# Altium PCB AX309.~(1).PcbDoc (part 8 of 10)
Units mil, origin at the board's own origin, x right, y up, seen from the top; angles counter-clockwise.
Board outline 5185 x 3614 mil, 4 copper layers (Top Layer, GND, Mid-Layer 1, Bottom Layer); 191 components, 352 nets, 1106 pads, 425 vias.
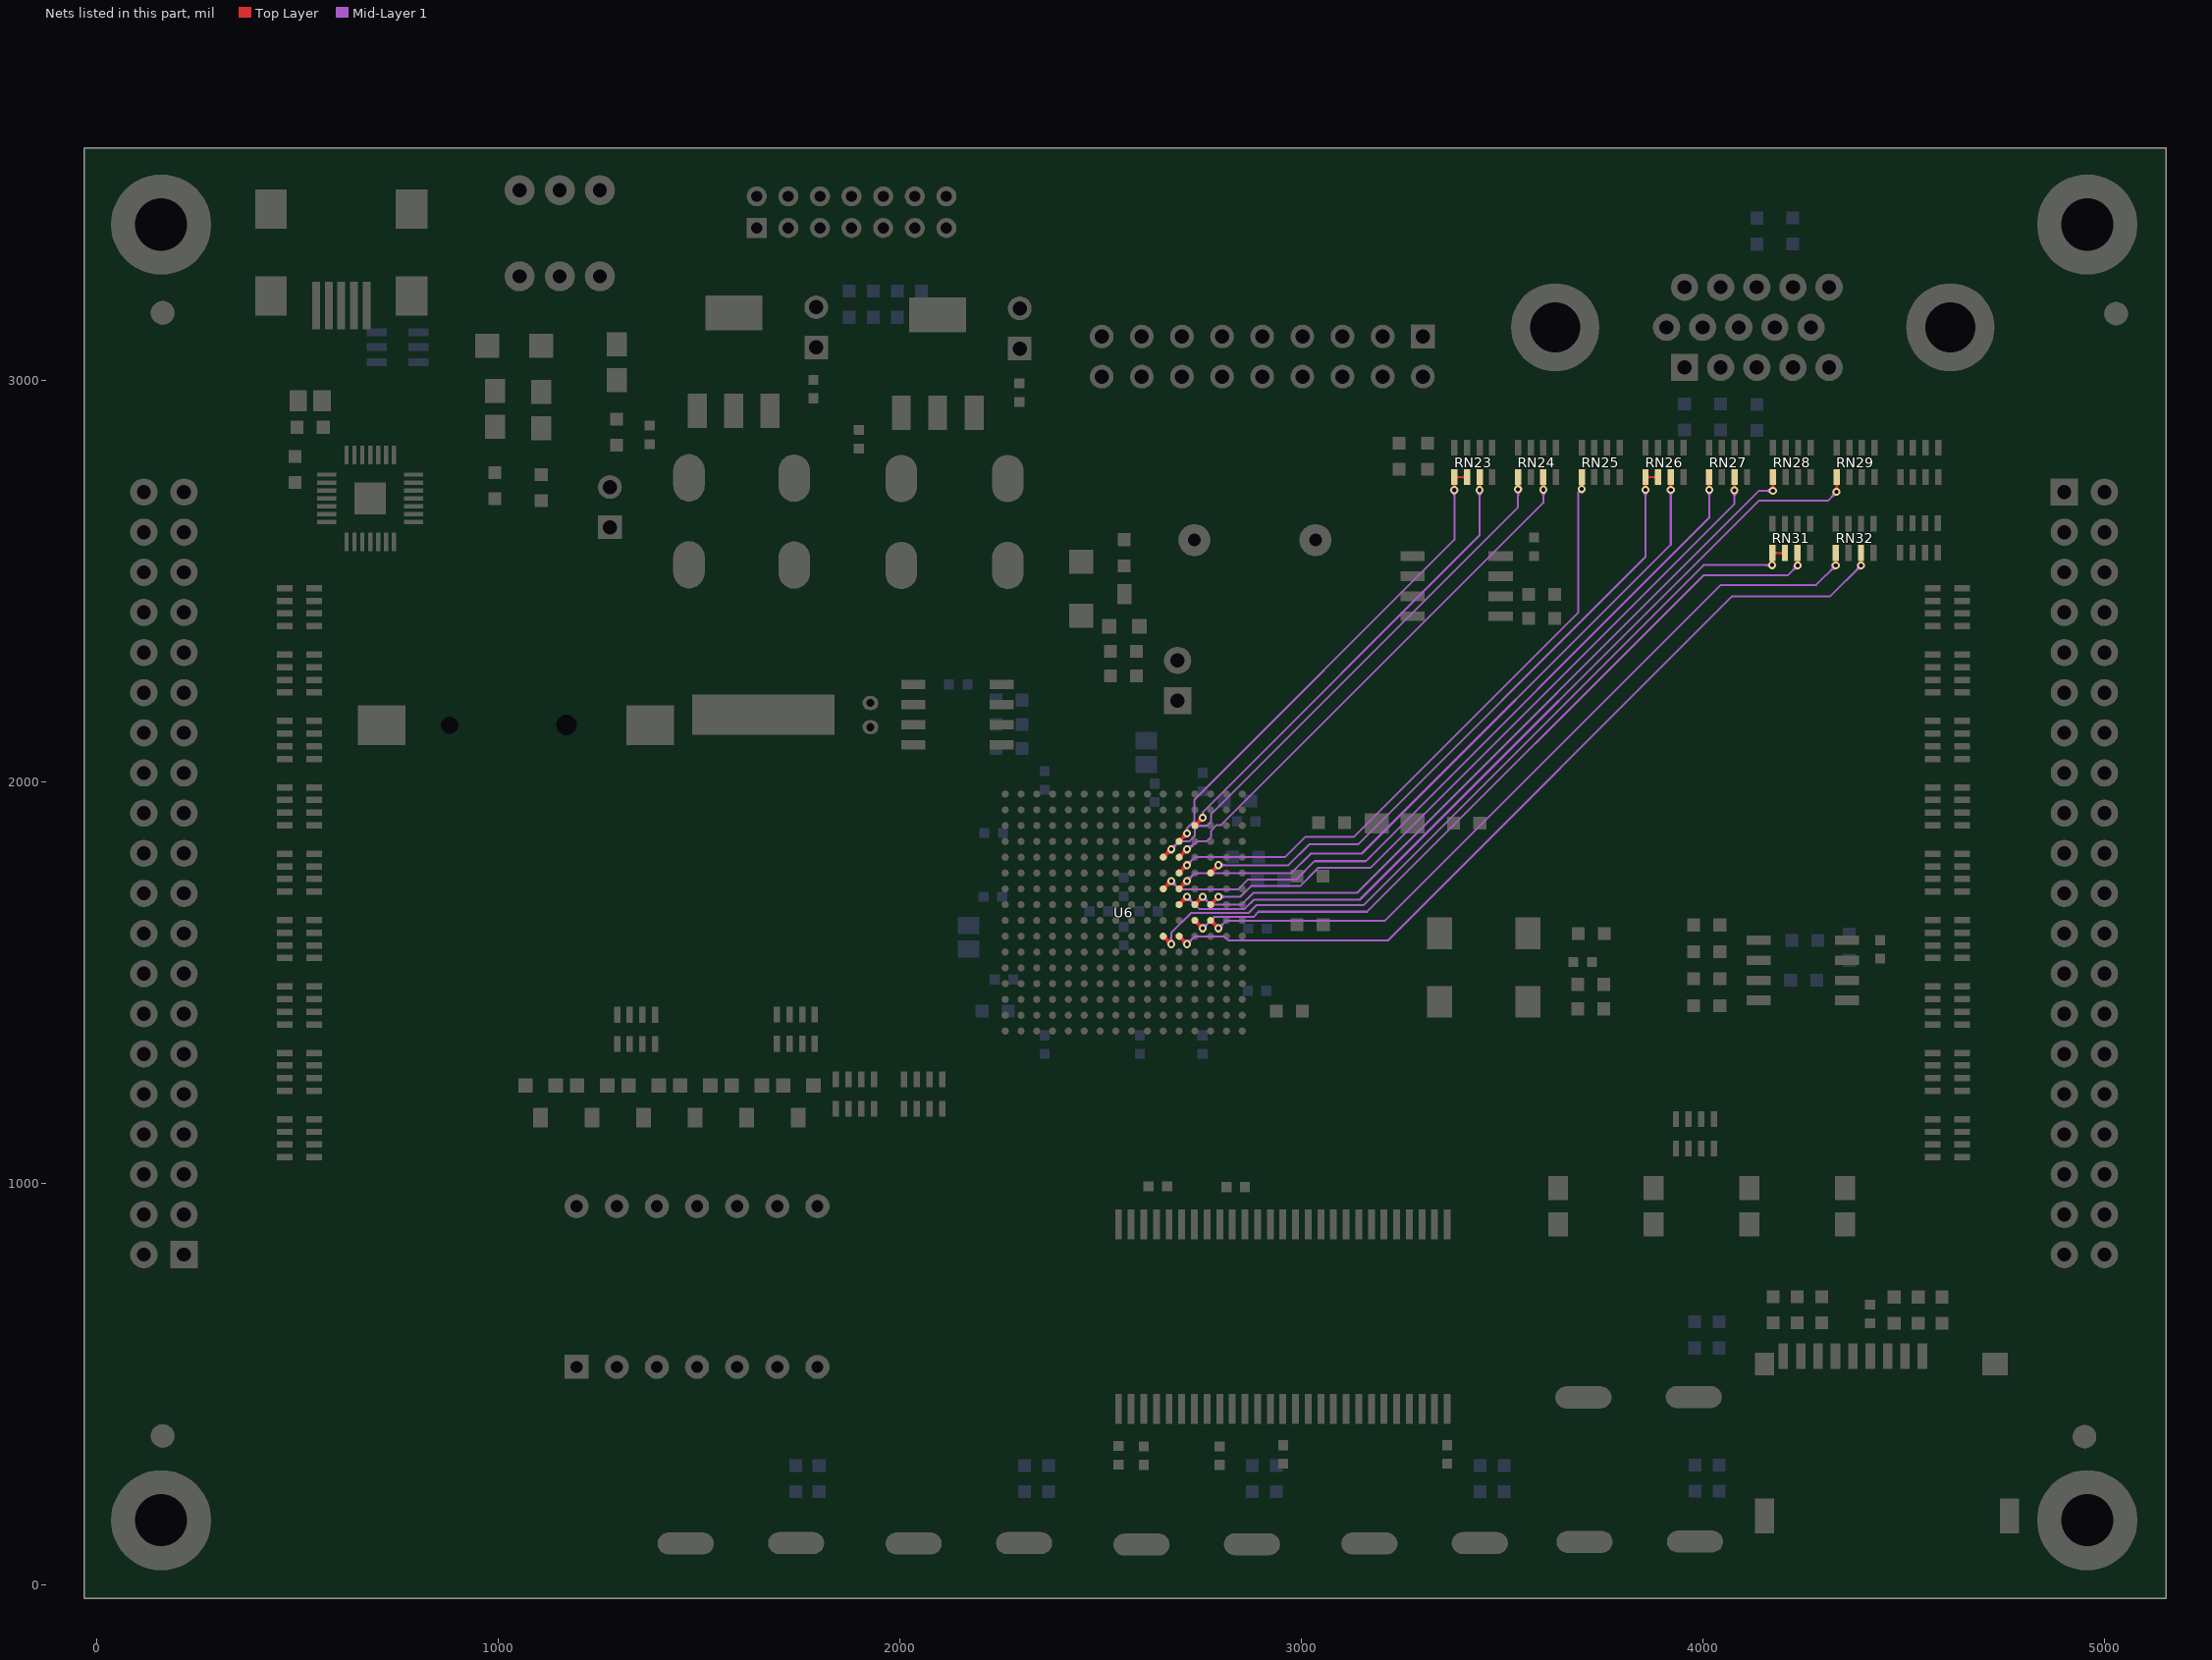
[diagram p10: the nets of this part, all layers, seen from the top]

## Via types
v1: diameter 20, hole 10, Top Layer to Bottom Layer, 328 vias
v2: diameter 30, hole 15, Top Layer to Bottom Layer, 95 vias
v3: diameter 40, hole 20, Top Layer to Bottom Layer, 2 vias

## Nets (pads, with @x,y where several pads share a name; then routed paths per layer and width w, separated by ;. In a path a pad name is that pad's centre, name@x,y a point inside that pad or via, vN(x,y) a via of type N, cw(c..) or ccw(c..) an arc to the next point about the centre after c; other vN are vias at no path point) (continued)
VGAD1: RN32.7 U6.M7 | length 2410.8
  Top Layer w5: U6.M7@2695.8,1608.59 cw(c2695.8,1593.24) 2706.65,1604.09 cw(c2717.5,1614.94) U6.M7@2702.15,1614.94 ; U6.M7@2695.8,1614.94 v1(2715.48,1595.26) ; U6.M7@2698.15,1609 cw(c2688.07,1591.54) v1@2708.05,1594.25 ; U6.M7@2701.74,1612.59 ccw(c2719.2,1622.67) v1@2716.49,1602.69 ; 2705.03,1605.02 cw(c2701.58,1599.04) v1@2708.24,1597.23 ; 2705.72,1605.71 ccw(c2711.7,1609.16) v1@2713.51,1602.5 ; 2706.84,1603.76 ccw(c2717.47,1609.9) v1@2715.82,1597.74 ; 2706.98,1603.9 cw(c2700.84,1593.27) v1@2713,1594.92 ; v1@2707.98,1595.26 ccw(c2689.87,1595.26) 2702.68,1608.06 ccw(c2715.48,1620.87) v1@2715.48,1602.76 ; v1@4389.2,2543.8 ccw(c4376.4,2556.6) 4394.5,2556.6 ccw(c4412.61,2556.6) v1@4399.81,2543.8 ; RN32.7@4390.7,2554.24 cw(c4381.53,2545.07) 4394.5,2545.07 cw(c4407.48,2545.07) RN32.7@4398.3,2554.24 ; v1@4391.89,2545.52 ccw(c4390.96,2548.02) 4393.53,2548.71 ccw(c4397.61,2549.8) v1@4396.49,2545.73 ; v1@4392.52,2545.73 ccw(c4391.4,2549.8) 4395.48,2548.71 ccw(c4398.05,2548.02) v1@4397.12,2545.52 ; v1(4394.5,2538.5) RN32.7@4394.5,2569.85 ; 2707.53,1602.56 cw(c2701.41,1599.03) 2708.24,1597.2 ccw(c2701.41,1599.03) 2707.53,1602.56 ; 2708.18,1603.21 ccw(c2711.71,1609.33) 2713.54,1602.5 cw(c2711.71,1609.33) 2708.18,1603.21
  Mid-Layer 1 w5: v1(2715.48,1595.26) 2734.22,1614 2809,1614 2818,1605 3217,1605 4074,2462 4318.01,2462 v1(4394.5,2538.5) ; v1@2715.48,1602.76 ccw(c2715.48,1620.87) 2728.28,1608.06 ccw(c2741.09,1595.26) v1@2722.98,1595.26 ; v1@4387,2538.5 cw(c4368.9,2538.5) 4381.7,2525.69 cw(c4394.5,2512.89) v1@4394.5,2531
VGAD2: RN32.5 U6.P8 | length 2245.3
  Top Layer w5: U6.P8@2774.54,1647.96 cw(c2774.54,1632.61) 2785.39,1643.46 cw(c2796.24,1654.32) U6.P8@2780.89,1654.32 ; U6.P8@2774.54,1654.32 v1(2794.22,1634.63) ; U6.P8@2776.89,1648.37 cw(c2766.81,1630.91) v1@2786.79,1633.62 ; U6.P8@2780.48,1651.96 ccw(c2797.94,1662.04) v1@2795.23,1642.06 ; 2783.77,1644.39 cw(c2780.32,1638.41) v1@2786.98,1636.6 ; 2784.46,1645.08 ccw(c2790.44,1648.53) v1@2792.25,1641.87 ; 2785.58,1643.13 ccw(c2796.21,1649.27) v1@2794.56,1637.11 ; 2785.72,1643.27 cw(c2779.58,1632.64) v1@2791.74,1634.29 ; v1@2786.72,1634.63 ccw(c2768.61,1634.63) 2781.42,1647.43 ccw(c2794.22,1660.24) v1@2794.22,1642.13 ; v1@4326.21,2543.79 ccw(c4313.41,2556.59) 4331.51,2556.59 ccw(c4349.62,2556.59) v1@4336.82,2543.79 ; RN32.5@4327.71,2554.24 cw(c4318.54,2545.07) 4331.51,2545.07 cw(c4344.49,2545.07) RN32.5@4335.31,2554.24 ; v1@4328.89,2545.52 ccw(c4327.96,2548.01) 4330.54,2548.7 ccw(c4334.62,2549.8) v1@4333.5,2545.72 ; v1@4329.52,2545.72 ccw(c4328.4,2549.8) 4332.49,2548.7 ccw(c4335.06,2548.01) v1@4334.13,2545.52 ; v1(4331.51,2538.49) RN32.5@4331.51,2569.85 ; 2786.27,1641.93 cw(c2780.15,1638.4) 2786.98,1636.57 ccw(c2780.15,1638.4) 2786.27,1641.93 ; 2786.92,1642.58 ccw(c2790.45,1648.7) 2792.28,1641.87 cw(c2790.45,1648.7) 2786.92,1642.58
  Mid-Layer 1 w5: v1(2794.22,1634.63) 2812.59,1653 3208,1653 4045,2490 4283.02,2490 v1(4331.51,2538.49) ; v1@2794.22,1642.13 ccw(c2794.22,1660.24) 2807.02,1647.43 ccw(c2819.83,1634.63) v1@2801.72,1634.63 ; v1@4324.01,2538.49 cw(c4305.91,2538.49) 4318.71,2525.68 cw(c4331.51,2512.88) v1@4331.51,2530.99
VGAD3: RN31.7 U6.N8 | length 2189.7
  Top Layer w5: U6.N8@2735.17,1647.96 cw(c2735.17,1632.61) 2746.02,1643.46 cw(c2756.87,1654.32) U6.N8@2741.52,1654.32 ; U6.N8@2735.17,1654.32 v1(2754.85,1634.63) ; U6.N8@2737.52,1648.37 cw(c2727.44,1630.91) v1@2747.42,1633.62 ; U6.N8@2741.11,1651.96 ccw(c2758.57,1662.04) v1@2755.86,1642.06 ; 2744.4,1644.39 cw(c2740.95,1638.41) v1@2747.61,1636.6 ; 2745.09,1645.08 ccw(c2751.07,1648.53) v1@2752.88,1641.87 ; 2746.21,1643.13 ccw(c2756.84,1649.27) v1@2755.19,1637.11 ; 2746.35,1643.27 cw(c2740.21,1632.64) v1@2752.37,1634.29 ; v1@2747.35,1634.63 ccw(c2729.24,1634.63) 2742.05,1647.43 ccw(c2754.85,1660.24) v1@2754.85,1642.13 ; v1@4231.2,2543.8 ccw(c4218.4,2556.6) 4236.5,2556.6 ccw(c4254.61,2556.6) v1@4241.81,2543.8 ; RN31.7@4232.7,2554.24 cw(c4223.53,2545.07) 4236.5,2545.07 cw(c4249.48,2545.07) RN31.7@4240.3,2554.24 ; v1@4233.89,2545.52 ccw(c4232.96,2548.02) 4235.53,2548.71 ccw(c4239.61,2549.8) v1@4238.49,2545.73 ; v1@4234.52,2545.73 ccw(c4233.4,2549.8) 4237.48,2548.71 ccw(c4240.05,2548.02) v1@4239.12,2545.52 ; v1(4236.5,2538.5) RN31.7@4236.5,2569.85 ; v1@2752.91,1641.87 cw(c2751.08,1648.7) 2747.55,1642.58 ccw(c2751.08,1648.7) v1@2752.91,1641.87 ; 2746.9,1641.93 cw(c2740.78,1638.4) 2747.61,1636.57 ccw(c2740.78,1638.4) 2746.9,1641.93
  Mid-Layer 1 w5: v1(2754.85,1634.63) 2783.22,1663 2881,1663 2894,1676 3164,1676 4002,2514 4212.01,2514 v1(4236.5,2538.5) ; v1@2754.85,1642.13 ccw(c2754.85,1660.24) 2767.65,1647.43 ccw(c2780.46,1634.63) v1@2762.35,1634.63 ; v1@4229,2538.5 cw(c4210.9,2538.5) 4223.7,2525.69 cw(c4236.5,2512.89) v1@4236.5,2531
VGAD4: RN31.5 RN31.6 U6.L7 | length 2293.1
  Top Layer w5: U6.L7@2656.43,1608.59 cw(c2656.43,1593.24) 2667.28,1604.09 cw(c2678.13,1614.94) U6.L7@2662.78,1614.94 ; U6.L7@2656.43,1614.94 v1(2676.11,1595.26) ; U6.L7@2658.78,1609 cw(c2648.7,1591.54) v1@2668.68,1594.25 ; U6.L7@2662.37,1612.59 ccw(c2679.83,1622.67) v1@2677.12,1602.69 ; 2665.66,1605.02 cw(c2662.21,1599.04) v1@2668.87,1597.23 ; 2666.35,1605.71 ccw(c2672.33,1609.16) v1@2674.14,1602.5 ; 2667.47,1603.76 ccw(c2678.1,1609.9) v1@2676.45,1597.74 ; 2667.61,1603.9 cw(c2661.47,1593.27) v1@2673.63,1594.92 ; v1@2668.61,1595.26 ccw(c2650.5,1595.26) 2663.31,1608.06 ccw(c2676.11,1620.87) v1@2676.11,1602.76 ; v1@4168.21,2544.79 ccw(c4155.41,2557.59) 4173.51,2557.59 ccw(c4191.62,2557.59) v1@4178.82,2544.79 ; RN31.5@4169.71,2554.24 cw(c4160.54,2545.07) 4173.51,2545.07 cw(c4186.49,2545.07) RN31.5@4177.31,2554.24 ; v1(4173.51,2539.49) RN31.5@4173.51,2569.85 RN31.6@4205.01,2569.85 ; RN31.5@4177.31,2566.05 cw(c4186.49,2556.88) 4186.49,2569.85 cw(c4186.49,2582.82) RN31.5@4177.31,2573.65 ; RN31.6@4201.21,2566.05 ccw(c4192.03,2556.88) 4192.03,2569.85 ccw(c4192.03,2582.82) RN31.6@4201.21,2573.65 ; v1@2674.17,1602.5 cw(c2672.34,1609.33) 2668.81,1603.21 ccw(c2672.34,1609.33) v1@2674.17,1602.5 ; 2668.16,1602.56 cw(c2662.04,1599.03) 2668.87,1597.2 ccw(c2662.04,1599.03) 2668.16,1602.56
  Mid-Layer 1 w5: v1@2670.81,1600.56 ccw(c2658,1613.37) 2676.11,1613.37 ccw(c2694.22,1613.37) v1@2681.41,1600.56 ; v1(2676.11,1595.26) 2676.11,1623.11 2726,1673 2869,1673 2888,1692 3155,1692 4002.49,2539.49 v1(4173.51,2539.49) ; v1@4168.21,2534.18 ccw(c4155.41,2521.38) 4155.41,2539.49 ccw(c4155.41,2557.59) v1@4168.21,2544.79
VGAD5: RN29.5 U6.M9 | length 2383.6
  Top Layer w5: U6.M9@2695.8,1693.68 v1(2715.48,1713.37) ; U6.M9@2695.8,1700.04 ccw(c2695.8,1715.39) 2706.65,1704.54 ccw(c2717.5,1693.68) U6.M9@2702.15,1693.68 ; U6.M9@2698.15,1699.63 ccw(c2688.07,1717.09) v1@2708.05,1714.38 ; U6.M9@2701.74,1696.04 cw(c2719.2,1685.96) v1@2716.49,1705.94 ; 2705.03,1703.61 ccw(c2701.58,1709.59) v1@2708.24,1711.4 ; 2705.72,1702.92 cw(c2711.7,1699.47) v1@2713.51,1706.13 ; 2706.84,1704.87 cw(c2717.47,1698.73) v1@2715.82,1710.89 ; 2706.98,1704.73 ccw(c2700.84,1715.36) v1@2713,1713.71 ; v1@2707.98,1713.37 cw(c2689.87,1713.37) 2702.68,1700.57 cw(c2715.48,1687.76) v1@2715.48,1705.87 ; v1@4328.49,2727.51 ccw(c4315.69,2740.31) 4333.8,2740.31 ccw(c4351.9,2740.31) v1@4339.1,2727.51 ; RN29.5@4330,2743.24 cw(c4320.82,2734.07) 4333.8,2734.07 cw(c4346.77,2734.07) RN29.5@4337.6,2743.24 ; v1(4333.8,2722.2) RN29.5@4333.8,2758.85 ; 2707.53,1706.07 ccw(c2701.41,1709.6) 2708.24,1711.43 cw(c2701.41,1709.6) 2707.53,1706.07 ; 2708.18,1705.42 cw(c2711.71,1699.3) 2713.54,1706.13 ccw(c2711.71,1699.3) 2708.18,1705.42
  Mid-Layer 1 w5: v1@2715.48,1705.87 cw(c2715.48,1687.76) 2728.28,1700.57 cw(c2741.09,1713.37) v1@2722.98,1713.37 ; v1(2715.48,1713.37) 2745.85,1683 2859,1683 2882,1706 3146,1706 4140,2700 4311.59,2700 v1(4333.8,2722.2) ; v1@4326.3,2722.2 cw(c4308.19,2722.2) 4320.99,2709.4 cw(c4333.8,2696.6) v1@4333.8,2714.7
VGAD6: RN28.5 U6.N9 | length 2199.6
  Top Layer w5: U6.N9@2735.17,1693.68 v1(2754.85,1713.37) ; U6.N9@2735.17,1700.04 ccw(c2735.17,1715.39) 2746.02,1704.54 ccw(c2756.87,1693.68) U6.N9@2741.52,1693.68 ; U6.N9@2737.52,1699.63 ccw(c2727.44,1717.09) v1@2747.42,1714.38 ; U6.N9@2741.11,1696.04 cw(c2758.57,1685.96) v1@2755.86,1705.94 ; 2744.4,1703.61 ccw(c2740.95,1709.59) v1@2747.61,1711.4 ; 2745.09,1702.92 cw(c2751.07,1699.47) v1@2752.88,1706.13 ; 2746.21,1704.87 cw(c2756.84,1698.73) v1@2755.19,1710.89 ; 2746.35,1704.73 ccw(c2740.21,1715.36) v1@2752.37,1713.71 ; v1@2747.35,1713.37 cw(c2729.24,1713.37) 2742.05,1700.57 cw(c2754.85,1687.76) v1@2754.85,1705.87 ; v1@4169.78,2730.22 ccw(c4156.98,2743.02) 4175.08,2743.02 ccw(c4193.19,2743.02) v1@4180.39,2730.22 ; RN28.5@4171.28,2743.24 cw(c4162.11,2734.07) 4175.08,2734.07 cw(c4188.06,2734.07) RN28.5@4178.88,2743.24 ; v1@4171.71,2731.62 ccw(c4168.19,2738.62) 4175.76,2736.59 ccw(c4179.7,2735.54) v1@4178.07,2731.8 ; v1@4172.09,2731.8 ccw(c4170.47,2735.54) 4174.41,2736.59 ccw(c4181.98,2738.62) v1@4178.45,2731.62 ; v1(4175.08,2724.92) RN28.5@4175.08,2758.85 ; v1@2752.91,1706.13 ccw(c2751.08,1699.3) 2747.55,1705.42 cw(c2751.08,1699.3) v1@2752.91,1706.13 ; 2746.9,1706.07 ccw(c2740.78,1709.6) 2747.61,1711.43 cw(c2740.78,1709.6) 2746.9,1706.07
  Mid-Layer 1 w5: v1@2754.85,1705.87 cw(c2754.85,1687.76) 2767.65,1700.57 cw(c2780.46,1713.37) v1@2762.35,1713.37 ; v1(2754.85,1713.37) 2774.22,1694 2852,1694 2881,1723 3139,1723 4140.92,2724.92 v1(4175.08,2724.92) ; v1@4169.78,2719.61 ccw(c4156.98,2706.81) 4156.98,2724.92 ccw(c4156.98,2743.02) v1@4169.78,2730.22
VGAD7: RN27.7 U6.P9 | length 2065.3
  Top Layer w5: U6.P9@2774.54,1693.68 v1(2794.22,1713.37) ; U6.P9@2774.54,1700.04 ccw(c2774.54,1715.39) 2785.39,1704.54 ccw(c2796.24,1693.68) U6.P9@2780.89,1693.68 ; U6.P9@2776.89,1699.63 ccw(c2766.81,1717.09) v1@2786.79,1714.38 ; U6.P9@2780.48,1696.04 cw(c2797.94,1685.96) v1@2795.23,1705.94 ; 2783.77,1703.61 ccw(c2780.32,1709.59) v1@2786.98,1711.4 ; 2784.46,1702.92 cw(c2790.44,1699.47) v1@2792.25,1706.13 ; 2785.58,1704.87 cw(c2796.21,1698.73) v1@2794.56,1710.89 ; 2785.72,1704.73 ccw(c2779.58,1715.36) v1@2791.74,1713.71 ; v1@2786.72,1713.37 cw(c2768.61,1713.37) 2781.42,1700.57 cw(c2794.22,1687.76) v1@2794.22,1705.87 ; v1@4074.06,2730.94 ccw(c4061.25,2743.75) 4079.36,2743.75 ccw(c4097.47,2743.75) v1@4084.66,2730.94 ; RN27.7@4075.56,2743.24 cw(c4066.39,2734.07) 4079.36,2734.07 cw(c4092.33,2734.07) RN27.7@4083.16,2743.24 ; v1@4076.35,2732.51 ccw(c4073.66,2738.64) 4080.12,2736.9 ccw(c4083.67,2735.95) v1@4082.25,2732.56 ; v1@4076.47,2732.56 ccw(c4075.05,2735.95) 4078.6,2736.9 ccw(c4085.07,2738.64) v1@4082.38,2732.51 ; v1(4079.36,2725.64) RN27.7@4079.36,2758.85 ; 2786.27,1706.07 ccw(c2780.15,1709.6) 2786.98,1711.43 cw(c2780.15,1709.6) 2786.27,1706.07 ; 2786.92,1705.42 cw(c2790.45,1699.3) 2792.28,1706.13 ccw(c2790.45,1699.3) 2786.92,1705.42
  Mid-Layer 1 w5: v1(2794.22,1713.37) 2848.37,1713.37 2875,1740 2997,1740 3042,1785 3172,1785 4079.36,2692.36 v1(4079.36,2725.64) ; v1@2799.52,1708.07 cw(c2812.33,1695.26) 2812.33,1713.37 cw(c2812.33,1731.48) v1@2799.52,1718.67 ; v1@4074.06,2720.34 cw(c4061.25,2707.53) 4079.36,2707.53 cw(c4097.47,2707.53) v1@4084.66,2720.34
VGAD8: RN27.5 U6.L10 | length 2136.3
  Top Layer w5: U6.L10@2656.43,1733.06 v1(2676.11,1752.74) ; U6.L10@2656.43,1739.41 ccw(c2656.43,1754.76) 2667.28,1743.91 ccw(c2678.13,1733.06) U6.L10@2662.78,1733.06 ; U6.L10@2658.78,1739 ccw(c2648.7,1756.46) v1@2668.68,1753.75 ; U6.L10@2662.37,1735.41 cw(c2679.83,1725.33) v1@2677.12,1745.31 ; 2665.66,1742.98 ccw(c2662.21,1748.96) v1@2668.87,1750.77 ; 2666.35,1742.29 cw(c2672.33,1738.84) v1@2674.14,1745.5 ; 2667.47,1744.24 cw(c2678.1,1738.1) v1@2676.45,1750.26 ; 2667.61,1744.1 ccw(c2661.47,1754.73) v1@2673.63,1753.08 ; v1@2668.61,1752.74 cw(c2650.5,1752.74) 2663.31,1739.94 cw(c2676.11,1727.13) v1@2676.11,1745.24 ; v1@4011.07,2732.67 ccw(c3998.26,2745.48) 4016.37,2745.48 ccw(c4034.48,2745.48) v1@4021.67,2732.67 ; RN27.5@4012.57,2743.24 cw(c4003.39,2734.07) 4016.37,2734.07 cw(c4029.34,2734.07) RN27.5@4020.17,2743.24 ; v1@4013.73,2734.39 ccw(c4012.77,2736.95) 4015.41,2737.65 ccw(c4019.63,2738.78) v1@4018.43,2734.58 ; v1@4014.31,2734.58 ccw(c4013.11,2738.78) 4017.33,2737.65 ccw(c4019.97,2736.95) v1@4019.01,2734.39 ; v1(4016.37,2727.37) RN27.5@4016.37,2758.85 ; v1@2674.17,1745.5 ccw(c2672.34,1738.67) 2668.81,1744.79 cw(c2672.34,1738.67) v1@2674.17,1745.5 ; 2668.16,1745.44 ccw(c2662.04,1748.97) 2668.87,1750.8 cw(c2662.04,1748.97) 2668.16,1745.44
  Mid-Layer 1 w5: v1@2676.11,1745.24 cw(c2676.11,1727.13) 2688.91,1739.94 cw(c2701.72,1752.74) v1@2683.61,1752.74 ; v1(2676.11,1752.74) 2696.85,1732 2843,1732 2867,1756 2987,1756 3033,1802 3161,1802 4016.37,2657.37 v1(4016.37,2727.37) ; v1@4011.07,2722.07 cw(c3998.26,2709.26) 4016.37,2709.26 cw(c4034.48,2709.26) v1@4021.67,2722.07
VGAD9: RN26.7 U6.M10 | length 2023.2
  Top Layer w5: U6.M10@2695.8,1733.06 v1(2715.48,1752.74) ; U6.M10@2695.8,1739.41 ccw(c2695.8,1754.76) 2706.65,1743.91 ccw(c2717.5,1733.06) U6.M10@2702.15,1733.06 ; U6.M10@2698.15,1739 ccw(c2688.07,1756.46) v1@2708.05,1753.75 ; U6.M10@2701.74,1735.41 cw(c2719.2,1725.33) v1@2716.49,1745.31 ; 2705.03,1742.98 ccw(c2701.58,1748.96) v1@2708.24,1750.77 ; 2705.72,1742.29 cw(c2711.7,1738.84) v1@2713.51,1745.5 ; 2706.84,1744.24 cw(c2717.47,1738.1) v1@2715.82,1750.26 ; 2706.98,1744.1 ccw(c2700.84,1754.73) v1@2713,1753.08 ; v1@2707.98,1752.74 cw(c2689.87,1752.74) 2702.68,1739.94 cw(c2715.48,1727.13) v1@2715.48,1745.24 ; v1@3915.34,2732.66 ccw(c3902.54,2745.46) 3920.65,2745.46 ccw(c3938.75,2745.46) v1@3925.95,2732.66 ; RN26.7@3916.85,2743.24 cw(c3907.67,2734.07) 3920.65,2734.07 cw(c3933.62,2734.07) RN26.7@3924.45,2743.24 ; v1@3918.01,2734.37 ccw(c3917.04,2736.94) 3919.69,2737.65 ccw(c3923.93,2738.78) v1@3922.72,2734.56 ; v1@3918.58,2734.56 ccw(c3917.37,2738.78) 3921.61,2737.65 ccw(c3924.25,2736.94) v1@3923.29,2734.37 ; v1(3920.65,2727.35) RN26.7@3920.65,2758.85 ; 2707.53,1745.44 ccw(c2701.41,1748.97) 2708.24,1750.8 cw(c2701.41,1748.97) 2707.53,1745.44 ; 2708.18,1744.79 cw(c2711.71,1738.67) 2713.54,1745.5 ccw(c2711.71,1738.67) 2708.18,1744.79
  Mid-Layer 1 w5: v1(2715.48,1752.74) 2735.17,1772.43 2774.54,1772.43 2975.43,1772.43 3024,1821 3151,1821 3920.65,2590.65 v1(3920.65,2727.35) ; v1@2715.48,1760.24 ccw(c2715.48,1778.35) 2728.28,1765.54 ccw(c2741.09,1752.74) v1@2722.98,1752.74 ; v1@3915.34,2722.05 cw(c3902.54,2709.25) 3920.65,2709.25 cw(c3938.75,2709.25) v1@3925.95,2722.05
VGAD10: RN26.5 RN26.6 U6.P11 | length 1961.1
  Top Layer w5: U6.P11@2774.54,1772.43 v1(2794.22,1792.11) ; U6.P11@2774.54,1778.78 ccw(c2774.54,1794.13) 2785.39,1783.28 ccw(c2796.24,1772.43) U6.P11@2780.89,1772.43 ; U6.P11@2776.89,1778.37 ccw(c2766.81,1795.83) v1@2786.79,1793.12 ; U6.P11@2780.48,1774.78 cw(c2797.94,1764.7) v1@2795.23,1784.68 ; 2783.77,1782.35 ccw(c2780.32,1788.33) v1@2786.98,1790.14 ; 2784.46,1781.66 cw(c2790.44,1778.21) v1@2792.25,1784.87 ; 2785.58,1783.61 cw(c2796.21,1777.47) v1@2794.56,1789.63 ; 2785.72,1783.47 ccw(c2779.58,1794.1) v1@2791.74,1792.45 ; v1@2786.72,1792.11 cw(c2768.61,1792.11) 2781.42,1779.31 cw(c2794.22,1766.5) v1@2794.22,1784.61 ; v1@3852.35,2732.65 ccw(c3839.55,2745.45) 3857.65,2745.45 ccw(c3875.76,2745.45) v1@3862.96,2732.65 ; RN26.5@3853.85,2743.24 cw(c3844.68,2734.07) 3857.65,2734.07 cw(c3870.63,2734.07) RN26.5@3861.45,2743.24 ; v1@3855.01,2734.36 ccw(c3854.05,2736.93) 3856.7,2737.64 ccw(c3860.94,2738.78) v1@3859.73,2734.55 ; v1@3855.58,2734.55 ccw(c3854.36,2738.78) 3858.61,2737.64 ccw(c3861.26,2736.93) v1@3860.3,2734.36 ; v1(3857.65,2727.35) RN26.5@3857.65,2758.85 ; RN26.5@3861.45,2755.05 cw(c3870.63,2745.88) 3870.63,2758.85 cw(c3870.63,2771.82) RN26.5@3861.45,2762.65 ; RN26.5@3862.51,2758.85 RN26.6@3889.15,2758.85 RN26.6@3894.01,2758.85 ; RN26.6@3885.35,2755.05 ccw(c3876.18,2745.88) 3876.18,2758.85 ccw(c3876.18,2771.82) RN26.6@3885.35,2762.65 ; v1@2786.98,1790.17 cw(c2780.15,1788.34) 2786.27,1784.81 ccw(c2780.15,1788.34) v1@2786.98,1790.17 ; 2786.92,1784.16 cw(c2790.45,1778.04) 2792.28,1784.87 ccw(c2790.45,1778.04) 2786.92,1784.16
  Mid-Layer 1 w5: v1@2798.11,1796 v1(2794.22,1792.11) 2968.11,1792.11 3020,1844 3142,1844 3857.65,2559.65 v1(3857.65,2727.35) ; v1@2799.52,1786.81 cw(c2812.33,1774) 2812.33,1792.11 cw(c2812.33,1810.22) v1@2799.52,1797.41 ; v1@3852.35,2722.04 cw(c3839.55,2709.24) 3857.65,2709.24 cw(c3875.76,2709.24) v1@3862.96,2722.04
VGAD11: RN25.5 U6.M11 | length 1833
  Top Layer w5: U6.M11@2695.8,1772.43 v1(2715.37,1792) ; U6.M11@2695.8,1778.78 ccw(c2695.8,1794.13) 2706.65,1783.28 ccw(c2717.5,1772.43) U6.M11@2702.15,1772.43 ; U6.M11@2698.17,1778.39 ccw(c2688.24,1795.59) v1@2707.93,1792.98 ; U6.M11@2701.76,1774.8 cw(c2718.96,1764.87) v1@2716.35,1784.56 ; 2705.05,1782.36 ccw(c2701.71,1788.16) v1@2708.15,1789.97 ; 2705.73,1781.68 cw(c2711.53,1778.34) v1@2713.34,1784.78 ; 2706.83,1783.59 cw(c2717.28,1777.56) v1@2715.7,1789.52 ; 2706.96,1783.46 ccw(c2700.93,1793.91) v1@2712.89,1792.33 ; v1@2707.87,1792 cw(c2689.76,1792) 2702.57,1779.2 cw(c2715.37,1766.39) v1@2715.37,1784.5 ; v1@3693.64,2734.36 ccw(c3680.83,2747.17) 3698.94,2747.17 ccw(c3717.05,2747.17) v1@3704.24,2734.36 ; RN25.5@3695.14,2743.24 cw(c3685.97,2734.07) 3698.94,2734.07 cw(c3711.91,2734.07) RN25.5@3702.74,2743.24 ; v1(3698.94,2729.06) RN25.5@3698.94,2758.85 ; 2707.41,1784.59 ccw(c2701.16,1788.19) 2708.13,1790.06 cw(c2701.16,1788.19) 2707.41,1784.59 ; 2707.96,1784.04 cw(c2711.56,1777.79) 2713.43,1784.76 ccw(c2711.56,1777.79) 2707.96,1784.04
  Mid-Layer 1 w5: v1(2715.37,1792) 2735.37,1812 2960,1812 3010,1862 3131,1862 3690,2421 3690,2720.12 v1(3698.94,2729.06) ; v1@2715.37,1799.5 ccw(c2715.37,1817.61) 2728.17,1804.8 ccw(c2740.98,1792) v1@2722.87,1792
VGAD12: RN24.7 U6.M12 | length 1617.4
  Top Layer w5: U6.M12@2695.8,1811.8 v1(2715.48,1831.48) ; U6.M12@2695.8,1818.15 ccw(c2695.8,1833.5) 2706.65,1822.65 ccw(c2717.5,1811.8) U6.M12@2702.15,1811.8 ; U6.M12@2698.15,1817.74 ccw(c2688.07,1835.2) v1@2708.05,1832.49 ; U6.M12@2701.74,1814.15 cw(c2719.2,1804.07) v1@2716.49,1824.05 ; 2705.03,1821.72 ccw(c2701.58,1827.7) v1@2708.24,1829.51 ; 2705.72,1821.03 cw(c2711.7,1817.58) v1@2713.51,1824.24 ; 2706.84,1822.98 cw(c2717.47,1816.84) v1@2715.82,1829 ; 2706.98,1822.84 ccw(c2700.84,1833.47) v1@2713,1831.82 ; v1@2707.98,1831.48 cw(c2689.87,1831.48) 2702.68,1818.68 cw(c2715.48,1805.87) v1@2715.48,1823.98 ; v1@3597.91,2733.09 ccw(c3585.11,2745.89) 3603.22,2745.89 ccw(c3621.32,2745.89) v1@3608.52,2733.09 ; RN24.7@3599.42,2743.24 cw(c3590.24,2734.07) 3603.22,2734.07 cw(c3616.19,2734.07) RN24.7@3607.02,2743.24 ; v1(3603.22,2727.78) RN24.7@3603.22,2758.85 ; 2707.53,1824.18 ccw(c2701.41,1827.71) 2708.24,1829.54 cw(c2701.41,1827.71) 2707.53,1824.18 ; 2708.18,1823.53 cw(c2711.71,1817.41) 2713.54,1824.24 ccw(c2711.71,1817.41) 2708.18,1823.53
  Mid-Layer 1 w5: v1(2715.48,1831.48) 2721.48,1831.48 2742,1852 2765,1852 2775,1862 2775,1877 2790,1892 2801,1892 3603.22,2694.22 v1(3603.22,2727.78) ; v1@2715.48,1833.98 ccw(c2715.48,1854.5) 2729.99,1839.99 ; v1@2715.48,1838.98 ccw(c2715.48,1871.57) 2738.53,1848.53 ; v1@3597.91,2722.48 cw(c3585.11,2709.68) 3603.22,2709.68 cw(c3621.32,2709.68) v1@3608.52,2722.48
VGAD13: RN24.5 U6.L12 | length 1597.5
  Top Layer w5: U6.L12@2656.43,1811.8 v1(2676.11,1831.48) ; U6.L12@2656.43,1818.15 ccw(c2656.43,1833.5) 2667.28,1822.65 ccw(c2678.13,1811.8) U6.L12@2662.78,1811.8 ; U6.L12@2658.78,1817.74 ccw(c2648.7,1835.2) v1@2668.68,1832.49 ; U6.L12@2662.37,1814.15 cw(c2679.83,1804.07) v1@2677.12,1824.05 ; 2665.66,1821.72 ccw(c2662.21,1827.7) v1@2668.87,1829.51 ; 2666.35,1821.03 cw(c2672.33,1817.58) v1@2674.14,1824.24 ; 2667.47,1822.98 cw(c2678.1,1816.84) v1@2676.45,1829 ; 2667.61,1822.84 ccw(c2661.47,1833.47) v1@2673.63,1831.82 ; v1@2668.61,1831.48 cw(c2650.5,1831.48) 2663.31,1818.68 cw(c2676.11,1805.87) v1@2676.11,1823.98 ; v1@3534.92,2734.08 ccw(c3522.12,2746.88) 3540.23,2746.88 ccw(c3558.33,2746.88) v1@3545.53,2734.08 ; RN24.5@3536.43,2743.24 cw(c3527.25,2734.07) 3540.23,2734.07 cw(c3553.2,2734.07) RN24.5@3544.03,2743.24 ; v1(3540.23,2728.77) RN24.5@3540.23,2758.85 ; v1@2674.17,1824.24 ccw(c2672.34,1817.41) 2668.81,1823.53 cw(c2672.34,1817.41) v1@2674.17,1824.24 ; 2668.16,1824.18 ccw(c2662.04,1827.71) 2668.87,1829.54 cw(c2662.04,1827.71) 2668.16,1824.18
  Mid-Layer 1 w5: v1(2676.11,1831.48) 2695.63,1851 2721,1851 2735,1865 2735,1880 2745,1890 2765,1890 2775,1900 2775,1918 3540.23,2683.23 v1(3540.23,2728.77) ; v1@2676.11,1838.98 ccw(c2676.11,1857.09) 2688.91,1844.28 ccw(c2701.72,1831.48) v1@2683.61,1831.48 ; v1@3534.92,2723.47 cw(c3522.12,2710.67) 3540.23,2710.67 cw(c3558.33,2710.67) v1@3545.53,2723.47
VGAD14: RN23.7 U6.N14 | length 1428.7
  Top Layer w5: U6.N14@2735.17,1890.54 v1(2754.85,1910.22) ; U6.N14@2735.17,1896.89 ccw(c2735.17,1912.24) 2746.02,1901.39 ccw(c2756.87,1890.54) U6.N14@2741.52,1890.54 ; U6.N14@2737.52,1896.48 ccw(c2727.44,1913.94) v1@2747.42,1911.23 ; U6.N14@2741.11,1892.89 cw(c2758.57,1882.81) v1@2755.86,1902.79 ; 2744.4,1900.46 ccw(c2740.95,1906.44) v1@2747.61,1908.25 ; 2745.09,1899.77 cw(c2751.07,1896.32) v1@2752.88,1902.98 ; 2746.21,1901.72 cw(c2756.84,1895.58) v1@2755.19,1907.74 ; 2746.35,1901.58 ccw(c2740.21,1912.21) v1@2752.37,1910.56 ; v1@2747.35,1910.22 cw(c2729.24,1910.22) 2742.05,1897.42 cw(c2754.85,1884.61) v1@2754.85,1902.72 ; v1@3439.2,2731.8 ccw(c3426.4,2744.6) 3444.5,2744.6 ccw(c3462.61,2744.6) v1@3449.81,2731.8 ; RN23.7@3440.7,2743.24 cw(c3431.53,2734.07) 3444.5,2734.07 cw(c3457.48,2734.07) RN23.7@3448.3,2743.24 ; v1@3441.73,2733.46 ccw(c3440.55,2736.44) 3443.64,2737.27 ; v1@3441.94,2733.55 ccw(c3440.08,2738.69) 3445.36,2737.27 ; 3443.64,2737.27 ccw(c3448.93,2738.69) v1@3447.06,2733.55 ; v1(3444.5,2726.5) RN23.7@3444.5,2758.85 ; 3445.36,2737.27 ccw(c3448.46,2736.44) v1@3447.28,2733.46 ; v1@2752.91,1902.98 ccw(c2751.08,1896.15) 2747.55,1902.27 cw(c2751.08,1896.15) v1@2752.91,1902.98 ; 2746.9,1902.92 ccw(c2740.78,1906.45) 2747.61,1908.28 cw(c2740.78,1906.45) 2746.9,1902.92
  Mid-Layer 1 w5: v1@2750.84,1916.56 ccw(c2746.22,1923.85) 2754.85,1923.85 ; v1(2754.85,1910.22) 2754.85,1923.85 ; v1@2758.86,1916.56 cw(c2763.49,1923.85) 2754.85,1923.85 ; v1@3439.2,2721.19 cw(c3426.4,2708.39) 3444.5,2708.39 cw(c3462.61,2708.39) v1@3449.81,2721.19 ; v1(3444.5,2726.5) 3444.5,2613.5 2754.85,1923.85
VGAD15: RN23.5 RN23.6 U6.M13 | length 1527.9
  Top Layer w5: U6.M13@2695.8,1851.17 v1(2715.48,1870.85) ; U6.M13@2695.8,1857.52 ccw(c2695.8,1872.87) 2706.65,1862.02 ccw(c2717.5,1851.17) U6.M13@2702.15,1851.17 ; U6.M13@2698.15,1857.11 ccw(c2688.07,1874.57) v1@2708.05,1871.86 ; U6.M13@2701.74,1853.52 cw(c2719.2,1843.44) v1@2716.49,1863.42 ; 2705.03,1861.09 ccw(c2701.58,1867.07) v1@2708.24,1868.88 ; 2705.72,1860.4 cw(c2711.7,1856.95) v1@2713.51,1863.61 ; 2706.84,1862.35 cw(c2717.47,1856.21) v1@2715.82,1868.37 ; 2706.98,1862.21 ccw(c2700.84,1872.84) v1@2713,1871.19 ; v1@2707.98,1870.85 cw(c2689.87,1870.85) 2702.68,1858.05 cw(c2715.48,1845.24) v1@2715.48,1863.35 ; v1@3376.21,2731.79 ccw(c3363.41,2744.59) 3381.51,2744.59 ccw(c3399.62,2744.59) v1@3386.82,2731.79 ; RN23.5@3377.71,2743.24 cw(c3368.54,2734.07) 3381.51,2734.07 cw(c3394.49,2734.07) RN23.5@3385.31,2743.24 ; v1@3378.74,2733.46 ccw(c3377.55,2736.44) 3380.65,2737.27 ccw(c3385.95,2738.69) v1@3384.08,2733.54 ; v1@3378.95,2733.54 ccw(c3377.07,2738.69) 3382.37,2737.27 ccw(c3385.47,2736.44) v1@3384.28,2733.46 ; v1(3381.51,2726.49) RN23.5@3381.51,2758.85 RN23.6@3413.01,2758.85 ; RN23.5@3385.31,2755.05 cw(c3394.49,2745.88) 3394.49,2758.85 cw(c3394.49,2771.82) RN23.5@3385.31,2762.65 ; RN23.6@3409.21,2755.05 ccw(c3400.03,2745.88) 3400.03,2758.85 ccw(c3400.03,2771.82) RN23.6@3409.21,2762.65 ; v1@2708.24,1868.91 cw(c2701.41,1867.08) 2707.53,1863.55 ccw(c2701.41,1867.08) v1@2708.24,1868.91 ; 2708.18,1862.9 cw(c2711.71,1856.78) 2713.54,1863.61 ccw(c2711.71,1856.78) 2708.18,1862.9
  Mid-Layer 1 w5: v1@2711.89,1877.44 ccw(c2708.6,1883.48) 2715.48,1883.48 ; v1(2715.48,1870.85) 2715.48,1883.48 ; v1@2719.07,1877.44 cw(c2722.36,1883.48) 2715.48,1883.48 ; v1@3376.21,2721.18 cw(c3363.41,2708.38) 3381.51,2708.38 cw(c3399.62,2708.38) v1@3386.82,2721.18 ; v1(3381.51,2726.49) 3381.51,2602.51 2734,1955 2734,1902 2715.48,1883.48
pads on no net: Designator13_2.1 Designator13_2_1.1 Designator13_2_2.1 Designator13_2_3.1 Designator17_2.1 Designator17_2_1.1 Designator17_2_2.1 Designator17_2_3.1 J1.4 J1.6 J1.7 J1.8 J1.9 J4.4 J4.9 J4.11 J4.12 J4.15 J4.16 J4.17 P5.12 P5.14 RN9.3 RN9.4 RN9.5 RN9.6 RN11.1 RN11.2 RN11.7 RN11.8 RN19.3 RN19.4 RN19.5 RN19.6 RN23.1 RN23.8 RN24.3 RN24.6 RN26.1 RN26.8 RN27.3 RN27.6 RN31.1 RN31.8 RN32.3 RN32.6 SW1.1 SW1.4 U2.4 U2.6 U4.0 U4.1 U4.2 U4.10 U4.11 U4.12 U4.13 U4.14 U4.15 U4.16 U4.17 U4.18 U4.19 U4.20 U4.21 U4.22 U4.23 U4.24 U4.27 U4.28 U6.K11 U9.40 U10.0 U14.10
copper on no net: | length 129806.3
